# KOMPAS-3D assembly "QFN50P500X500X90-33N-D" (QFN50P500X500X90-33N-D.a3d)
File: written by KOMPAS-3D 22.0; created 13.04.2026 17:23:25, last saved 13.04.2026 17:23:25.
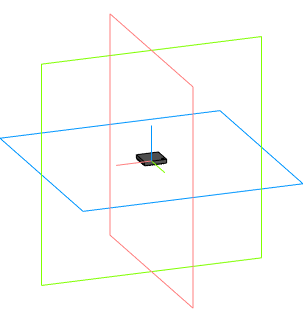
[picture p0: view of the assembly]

Document properties: Автор: Andrey; Полное имя файла: C:\Users\User1\Documents\QFN50P500X500X90-33N-D.a3d

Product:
- Component [assembly]: ASSEMBLY  | qty 1  | source file: ASSEMBLY.a3d
- Part/product: QFN50P500X500X90-33N-D
    Комментарий: QFN50P500X500X90-33N-D

Expressions: QFN50P500X500X90-33N-D
Referenced files in C:\Users\User1\Documents\: ASSEMBLY.a3d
